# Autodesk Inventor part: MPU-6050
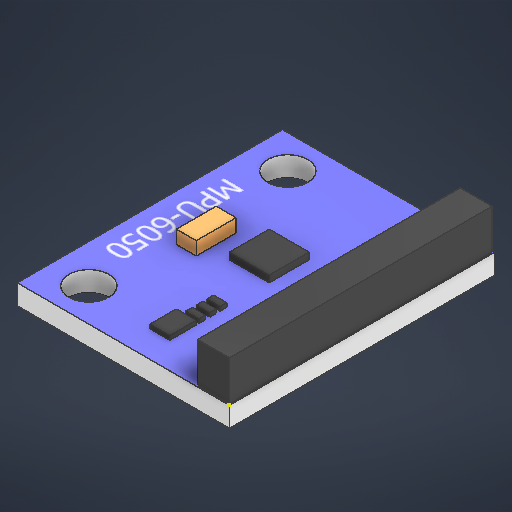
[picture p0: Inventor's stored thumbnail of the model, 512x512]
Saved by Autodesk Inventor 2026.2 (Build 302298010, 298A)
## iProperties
Created: 2026-04
Part Number: MPU-6050
Material: ABS 플라스틱
Document SubType Name: Modeling
Designer: work
Density: 1.06 g/cm^3
Appearance: 매끄러움 - 흰색
Author: work
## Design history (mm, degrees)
sketch "스케치1"
  geometry: L1 (0, 0)-(16, 0); L2 (16, 0)-(16, -20); L3 (16, -20)-(0, -20); L4 (0, -20)-(0, 0); L5 (13.1, -2.5)-(13.1, -17.5); L6 (16, -10)-(0, -10); C1 r 1.5 at (13.1, -2.5); C2 r 1.5 at (13.1, -17.5); 1 further point
  constraints: 12 end point, 3 midpoint, 2 centre point, 2 parallel, 1 horizontal, 1 perpendicular, 1 point on line, 1 vertical
  dimensions: "d0" = 16 distance of L2.end L3.end; "d1" = 20 distance of L1.end L2.end; "d2" = 3 diameter of C1; "d3" = 3 diameter of C2; "d4" = 15 distance of L5.start L5.end; "d5" = 2.9 distance between parallel lines of L2 L5
extrude "돌출1" new body sketch "스케치1" distance "d6" = 1.5; taper "d7" = 0 deg
sketch "스케치2"
  geometry: L1 (-2.5, 0.1)-(-0.1, 0.1); L2 (-0.1, 0.1)-(-0.1, 19.9); L3 (-0.1, 19.9)-(-2.5, 19.9); L4 (-2.5, 19.9)-(-2.5, 0.1); L5 (0, 0)-(0, 20) reference; L6 (0, 10)-(-16, 10); L7 (-16, 20)-(-16, 0) reference; L8 (0, 20)-(-16, 20) reference; L9 (-12.5, 8.5)-(-11, 8.5); L10 (-11, 8.5)-(-11, 11.5); L11 (-11, 11.5)-(-12.5, 11.5); L12 (-12.5, 11.5)-(-12.5, 8.5); L13 (-9.5, 9.5)-(-6.5, 9.5); L14 (-6.5, 9.5)-(-6.5, 12.5); L15 (-6.5, 12.5)-(-9.5, 12.5); L16 (-9.5, 12.5)-(-9.5, 9.5); L17 (-8, 9.5)-(-8, 12.5); L18 (-8, 2)-(-6.5, 2); L19 (-6.5, 2)-(-6.5, 4); L20 (-6.5, 4)-(-8, 4); L21 (-8, 4)-(-8, 2); L22 (-16, 0)-(0, 0) reference; L23 (-7.5, 4.2)-(-6.5, 4.2); L24 (-6.5, 4.2)-(-6.5, 4.7); L25 (-6.5, 4.7)-(-7.5, 4.7); L26 (-7.5, 4.7)-(-7.5, 4.2); L27 (-7.5, 5)-(-6.5, 5); L28 (-6.5, 5)-(-6.5, 5.5); L29 (-7.5, 5.5)-(-7.5, 5); L30 (-6.5, 5.5)-(-7.5, 5.5); L31 (-7.5, 5.8)-(-6.5, 5.8); L32 (-6.5, 5.8)-(-6.5, 6.3); L33 (-7.5, 6.3)-(-7.5, 5.8); L34 (-6.5, 6.3)-(-7.5, 6.3); 7 further points
  constraints: 60 end point, 14 parallel, 11 midpoint, 7 horizontal, 7 perpendicular, 3 point on line, 2 collinear
  dimensions: "d8" = 2.4 distance of L2.end L3.end; "d9" = 0.1 distance between parallel lines of L8 L3; "d10" = 0.1 distance between parallel lines of L5 L2; "d11" = 1.5 distance of L10.end L11.end; "d12" = 3 distance of L11.end L9.start; "d13" = 3.5 distance between parallel lines of L7 L12; "d14" = 3 distance of L15.end L14.end; "d15" = 3 distance of L14.end L13.end; "d16" = 0.5 distance of L17.start point (-8, 10); "d17" = 2 distance of L20.end L18.start; "d18" = 1.5 distance of L19.end L20.end; "d19" = 2 distance from line of L22 point (-7.25, 2); "d20" = 4 distance from line of L4 point (-6.5, 3); "d21" = 0.5 distance of L23.end L24.end; "d22" = 1 distance of L24.end L25.end; "d23" = 0.2 vertical distance of point (-7.25, 4) L23.end; "d24" = 4 distance from line of L4 L24.end; "d25" = 0.5 distance of L27.end L28.end; "d26" = 1 distance of L28.end L29.start; "d27" = 0.3 distance between parallel lines of L25 L27; "d28" = 0.5 distance of L31.end L32.end; "d29" = 1 distance of L32.end L33.start; "d30" = 0.3 distance from line of point (-7, 5.5) L31
extrude "돌출2" join sketch "스케치2" distance "d31" = 0.5; taper "d32" = 0 deg
extrude "돌출3" join sketch "스케치2" distance "d33" = 1; taper "d34" = 0 deg
extrude "돌출4" join sketch "스케치2" distance "d35" = 0.3; taper "d36" = 0 deg
extrude "돌출5" join sketch "스케치2" distance "d37" = 3; taper "d38" = 0 deg
sketch "스케치3" dims "d0" = 16, "d1" = 20, "d2" = 3, "d3" = 3, "d4" = 15, "d5" = 2.9
  geometry: L1 (-13.484, 14.73)-(-13.484, 5.398); L2 (-13.484, 5.398)-(-15.046, 5.398); L3 (-15.046, 5.398)-(-15.046, 14.73); L4 (-15.046, 14.73)-(-13.484, 14.73); 1 further point
  constraints: 2 other
node "솔리드1"
